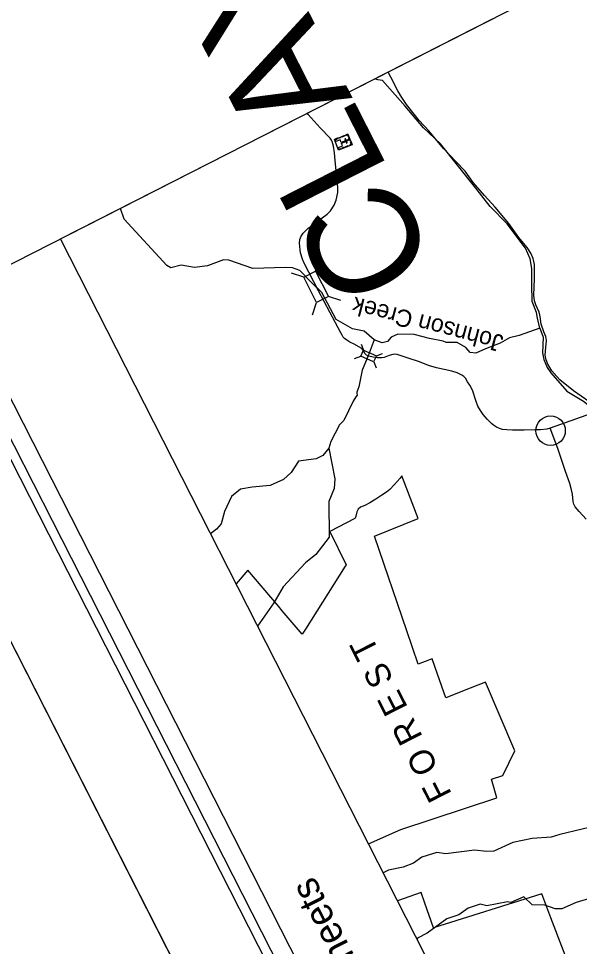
# Model space of a CAD drawing. Extents: x 558484 to 564063, y 513718 to 518374.
# Drawn here: x 559153.7 to 559306.6, y 514849.4 to 515102.2 of the extents above; entities that cross this region are included whole.
import ezdxf

# ---------------------------------------------------------------- set-up
doc = ezdxf.new("R2010")
doc.units = 0
for name, color, linetype in [('Default', 7, 'Continuous'), ('Prop Shade Heavy', 7, 'Continuous'), ('Scratch_Level_3', 7, 'Continuous'), ('Sheet Cutting Line CELL', 7, 'Continuous'), ('Sheet Data Field CELL', 7, 'Continuous'), ('Sheet Plot Border Inside CELL', 7, 'Continuous'), ('Sheet Plot Border Outside CELL', 7, 'Continuous'), ('Sheet Title CELL', 7, 'Continuous')]:
    doc.layers.add(name, color=color, linetype=linetype)

msp = doc.modelspace()

# ---------------------------------------------------------------- linework, layer by layer
at = {"layer": 'Default'}
for p, q in [((559234.64, 515033.36), (559235.73, 515036.72)), ((559231.48, 515031.75), (559228.12, 515032.85)), ((559241.57, 515025.39), (559238.21, 515026.48)), ((559233.89, 515021.48), (559234.98, 515024.84)), ((559247.1, 515013.54), (559247.73, 515011.88)), ((559245.34, 515009.6), (559246.99, 515010.23)), ((559251.26, 515010.29), (559252.91, 515010.92)), ((559250.54, 515008.68), (559251.17, 515007.03)), ((559312.6, 514995.58), (559298.66, 514990.63))]:
    msp.add_line(p, q, dxfattribs=at)
for points in [[(559363.74, 514652.18), (559165.18, 515042.19), (559493.11, 515209.15), (559691.68, 514819.14)], [(559363.74, 514652.18), (559165.18, 515042.19), (559493.11, 515209.15), (559691.68, 514819.14)], [(559243.53, 515070.75), (559244.67, 515067.86), (559240.96, 515066.4), (559239.83, 515069.3)], [(559240.02, 515068.82), (559240.18, 515068.89), (559240.06, 515069.21), (559240.65, 515069.44), (559240.58, 515069.6), (559239.83, 515069.3)], [(559240.07, 515068.67), (559240.71, 515067.04), (559242.03, 515067.56), (559241.74, 515068.3), (559242.93, 515068.76), (559243.11, 515068.28), (559243.27, 515068.34), (559243.09, 515068.82), (559243.7, 515069.06), (559243.63, 515069.23), (559243.02, 515068.99), (559242.83, 515069.47), (559242.67, 515069.41), (559242.86, 515068.93), (559241.67, 515068.47), (559241.39, 515069.19)], [(559240.84, 515069.7), (559241.47, 515069.95), (559241.54, 515069.78), (559240.91, 515069.53)], [(559241.82, 515070.08), (559242.45, 515070.33), (559242.52, 515070.16), (559241.89, 515069.92)], [(559242.9, 515070.51), (559242.97, 515070.34), (559243.43, 515070.52), (559243.66, 515069.93), (559243.83, 515070), (559243.53, 515070.75)], [(559243.95, 515069.67), (559244.25, 515068.92), (559244.08, 515068.86), (559243.79, 515069.61)], [(559244.03, 515067.61), (559243.97, 515067.77), (559244.44, 515067.96), (559244.21, 515068.55), (559244.37, 515068.61), (559244.66, 515067.85)], [(559240.77, 515066.89), (559240.94, 515066.95), (559241.06, 515066.63), (559241.65, 515066.86), (559241.72, 515066.7), (559240.96, 515066.4)], [(559241.95, 515066.98), (559242.58, 515067.23), (559242.64, 515067.06), (559242.01, 515066.82)], [(559242.91, 515067.36), (559243.54, 515067.6), (559243.6, 515067.44), (559242.97, 515067.19)], [(559234.98, 515024.84), (559231.47, 515031.75), (559234.69, 515033.39), (559238.21, 515026.48)], [(559247.73, 515011.88), (559251.26, 515010.3), (559250.52, 515008.65), (559246.99, 515010.23)]]:
    msp.add_lwpolyline(points, close=True, dxfattribs=at)
for points in [[(559309.17, 514997.9), (559305.04, 515000.79), (559301.31, 515003.8), (559300.42, 515004.7), (559299.13, 515006.21), (559298, 515008.04), (559297.55, 515009.2), (559297.3, 515010.48), (559297.42, 515012.6), (559297.6, 515014.5), (559297.5, 515015.6), (559296.9, 515016.91), (559296.14, 515018.99), (559295.94, 515021.06), (559295.65, 515022.19), (559294.75, 515024.24), (559294.39, 515025.33), (559294.15, 515026.85), (559294.4, 515031.35), (559294.34, 515035.24), (559294.01, 515036.86), (559293.36, 515038.27), (559292.35, 515039.85), (559290.14, 515042.61), (559287.37, 515046.4), (559283.61, 515050.88), (559280.77, 515053.99), (559277.61, 515057.6), (559275.47, 515060.63), (559272.96, 515063.3), (559269.58, 515066.86), (559265.58, 515071.65), (559262.91, 515074.49), (559261.53, 515076.16), (559259.51, 515078.84), (559258.23, 515080.72), (559257.09, 515082.52), (559255.2, 515086.26), (559254.48, 515087.66)], [(559295.85, 515017.9), (559295.19, 515020.62), (559294.9, 515022.1), (559293.71, 515025.09), (559293.61, 515029.75), (559293.66, 515034.13), (559293.18, 515036.77), (559291.89, 515039.68), (559286.92, 515046.29), (559282.26, 515051.06), (559278.4, 515056.02), (559268.75, 515068.09), (559264.09, 515072.42), (559259.13, 515078.32), (559252.96, 515085.39), (559251.66, 515085.57), (559250.81, 515085.79)], [(559231.57, 515035.58), (559231.09, 515036.65), (559230.59, 515038.4), (559230.49, 515039.22), (559230.34, 515041.04), (559230.45, 515042.04), (559230.73, 515042.92), (559231.29, 515043.76), (559232.62, 515045.06), (559233.58, 515045.75), (559234.78, 515046.64), (559237.88, 515048.89), (559238.78, 515049.81), (559239.76, 515051.34), (559240.34, 515052.76), (559240.78, 515054.86), (559240.74, 515056.33), (559240.6, 515057.92), (559240.05, 515063.57), (559239.88, 515065.64), (559239.57, 515067.42), (559239.21, 515068.75), (559239.04, 515069.09), (559238.67, 515069.64), (559235.92, 515072.49), (559232.66, 515076.1), (559232.39, 515076.41)], [(559182.48, 515047.57), (559181.52, 515050.51)], [(559244.79, 515017.7), (559240.29, 515020.2), (559236.38, 515027.57), (559233.46, 515030.42), (559230.45, 515033.6), (559228.44, 515034.32), (559226.53, 515034.41), (559217.62, 515034.11), (559211.03, 515036.43), (559209.58, 515036.49), (559205.21, 515034.82), (559201.68, 515034.36), (559198.1, 515035.04), (559195.26, 515034.33), (559194.15, 515034.98), (559182.48, 515047.57)], [(559248.99, 515010.31), (559248.56, 515010.51), (559248.23, 515010.84), (559247.64, 515011.88), (559247.26, 515012.36), (559245.22, 515013.54), (559244.06, 515014.08), (559243.25, 515014.59), (559242.62, 515015.07), (559242.26, 515015.45), (559241.93, 515015.96), (559241.6, 515016.57), (559238.6, 515022.21), (559235.48, 515028.05), (559231.57, 515035.58)], [(559295.85, 515017.9), (559290.19, 515015.85), (559287.56, 515015.23), (559285.02, 515013.76), (559280.98, 515012.23), (559278.38, 515011.06), (559276.83, 515011.27), (559275.65, 515012.6), (559273.29, 515013.92), (559270.33, 515013.97), (559269.48, 515014.3), (559265.71, 515015.03), (559261.59, 515016.11), (559257.09, 515016.19), (559255.31, 515015.39), (559254.28, 515014.26), (559252.83, 515013.88), (559250.66, 515014.67)], [(559295.85, 515017.9), (559296.77, 515015.43), (559296.56, 515011.17), (559296.9, 515009.3), (559297.78, 515007.14), (559298.85, 515005.69), (559303.22, 515000.72), (559307.74, 514998.01), (559309.87, 514996.27), (559310.89, 514994.94)], [(559250.66, 515014.67), (559247.98, 515017.07), (559244.79, 515017.7)], [(559250.66, 515014.67), (559248.99, 515010.31)], [(559248.99, 515010.31), (559247.37, 515006.4), (559246.52, 515001.85), (559245.92, 515000.46), (559245.98, 515000.12), (559246.06, 514999.6), (559245.65, 514999.15), (559244.95, 514998.01), (559242.37, 514992.73), (559241.21, 514991.49), (559238.83, 514987), (559238.33, 514985.21)], [(559298.66, 514990.63), (559297.72, 514990.34), (559296.03, 514990.15), (559294.46, 514990.2), (559291.59, 514990.08), (559288.36, 514990.05), (559286.84, 514990.13), (559285.64, 514990.25), (559284.82, 514990.49), (559284.01, 514990.86), (559283.18, 514991.44), (559282.65, 514991.86), (559281.45, 514993.11), (559280.38, 514994.36), (559279.64, 514995.39), (559278.94, 514996.59), (559278.45, 514997.87), (559277.48, 515000.97), (559276.76, 515002.31), (559276.15, 515003.29), (559275.56, 515004.22), (559275.09, 515004.71), (559274.57, 515005.05), (559273.31, 515005.73), (559271.81, 515006.12), (559267.67, 515007.09), (559265.5, 515007.73), (559263.01, 515008.66), (559259.95, 515009.65), (559256.89, 515010.66), (559256.34, 515010.77), (559255.75, 515010.73), (559254.75, 515010.41), (559253.37, 515009.88), (559252.79, 515009.78), (559252.09, 515009.76), (559251.56, 515009.79), (559250.35, 515009.93), (559249.23, 515010.2), (559248.99, 515010.31)], [(559308.46, 514965.79), (559306.51, 514967.92), (559305.99, 514968.51), (559305.46, 514969.22), (559305.13, 514969.9), (559304.92, 514970.66), (559304.71, 514972.68), (559304.49, 514973.78), (559303.97, 514975.57), (559302.85, 514978.82), (559300.74, 514985.09), (559298.66, 514990.63)], [(559238.33, 514985.21), (559236.63, 514983.16), (559234.85, 514982.25), (559230, 514981.6), (559228.02, 514978.51), (559225.91, 514976.59), (559222.34, 514975.04), (559217.45, 514974.51), (559214.23, 514973.99), (559211.77, 514971.98), (559209.86, 514967.91), (559208.94, 514964.58), (559207.73, 514963.09), (559206.07, 514961.87)], [(559238.33, 514985.21), (559239.99, 514976.82), (559239.75, 514974.15), (559238.32, 514970.65), (559238.44, 514960.88)], [(559249.11, 514877.34), (559257.89, 514881.28), (559284.11, 514889.88), (559282.64, 514894.97), (559285.72, 514895.98), (559289.04, 514902.72), (559281.02, 514921.43), (559274.78, 514918.94), (559273.63, 514918.48), (559270.24, 514917.13), (559267.97, 514923.55), (559266.49, 514927.76), (559262.63, 514926.35), (559259.55, 514935.41), (559250.8, 514961.2), (559262.63, 514966.02), (559258.21, 514977.63), (559257.79, 514977.04), (559256.14, 514975.14), (559254.93, 514973.91), (559254.05, 514973.2), (559252.77, 514972.4), (559251.15, 514971.25), (559249.46, 514970.3), (559248.14, 514969.55), (559246.96, 514969.14), (559246.28, 514968.53), (559245.97, 514967.78), (559245.7, 514966.67), (559245.63, 514966.39), (559245.6, 514966.35)], [(559245.6, 514966.35), (559245.36, 514966.02), (559238.61, 514962.48), (559243.03, 514953.39), (559242.77, 514952.99), (559231.99, 514935.9), (559231.08, 514934.45), (559225.62, 514940.87), (559224.56, 514942.11), (559216.22, 514951.91), (559213.01, 514948.24)], [(559238.44, 514960.88), (559234.73, 514956.19), (559231.99, 514953.96), (559225.86, 514947.35), (559223.32, 514943.07), (559218.9, 514936.68)], [(559313.47, 514882.86), (559301.23, 514879.93), (559298.87, 514879.15), (559293.73, 514878.84), (559288.5, 514877.77), (559283.26, 514875.41), (559281.34, 514875.27), (559278.04, 514875.63), (559270.19, 514874.67), (559267.75, 514875), (559263.65, 514873.73), (559261.35, 514872.12), (559258.58, 514871.02), (559254.54, 514870.21), (559253.1, 514869.49)], [(559306.18, 514838.03), (559298.85, 514857.17), (559296.33, 514863.75), (559266.8, 514854.46), (559264.51, 514861.22), (559263.51, 514864.15), (559257.02, 514861.81)], [(559310.01, 514862.61), (559305.7, 514861.39), (559301.82, 514859.65), (559300.03, 514859.69), (559297.17, 514860.69), (559293.74, 514860.72), (559291.45, 514862.97), (559287.9, 514861.37), (559286.97, 514861.53), (559281.35, 514860.43), (559279.53, 514860.89), (559276.28, 514859.86), (559273.71, 514857.99), (559270.45, 514856.95), (559265.14, 514853), (559262.44, 514851.64), (559262.34, 514851.36)]]:
    msp.add_lwpolyline(points, dxfattribs=at)
at = {"layer": 'Prop Shade Heavy'}
msp.add_circle((559298.76, 514989.94), 4.01, dxfattribs=at)
at = {"layer": 'Scratch_Level_3'}
msp.add_line((559282.83, 515102.09), (559012.78, 514964.6), dxfattribs=at)
at = {"layer": 'Sheet Cutting Line CELL'}
msp.add_line((559410.15, 514424.68), (558646.11, 515925.37), dxfattribs=at)
at = {"layer": 'Sheet Plot Border Inside CELL'}
msp.add_lwpolyline([(560364.51, 514925.16), (559608.41, 516410.26), (558668.16, 515931.55), (559424.26, 514446.45)], close=True, dxfattribs=at)
at = {"layer": 'Sheet Plot Border Outside CELL'}
msp.add_lwpolyline([(558646.11, 515925.37), (559410.15, 514424.68), (560390.41, 514923.75), (559626.36, 516424.45)], close=True, dxfattribs=at)
at = {"layer": 'Sheet Title CELL'}
for points in [[(558680.63, 515912.67), (559352.12, 514593.74)], [(558687.36, 515910.47), (559331.62, 514645.05)]]:
    msp.add_lwpolyline(points, dxfattribs=at)

# ---------------------------------------------------------------- texts
at = {"layer": 'Default'}
for s, height, rotation, p in [('Johnson Creek', 4.6875, 165.3641, (559286.2, 515015.8)), ('F O R E S T ', 6.7187, 116.9819, (559271.95, 514890.94))]:
    msp.add_text(s, height=height, rotation=rotation, dxfattribs=at).set_placement(p)
at = {"layer": 'Sheet Data Field CELL'}
msp.add_text('         CLAY COUNTY         ', height=30, rotation=116.9819, dxfattribs=at).set_placement((559313.61, 514945.44))
at = {"layer": 'Sheet Title CELL'}
msp.add_text('See Sheet 1-A For Index of Sheets', height=7.5, rotation=116.9819, dxfattribs=at).set_placement((559304.76, 514730.22))

doc.saveas('drawing.dxf')
